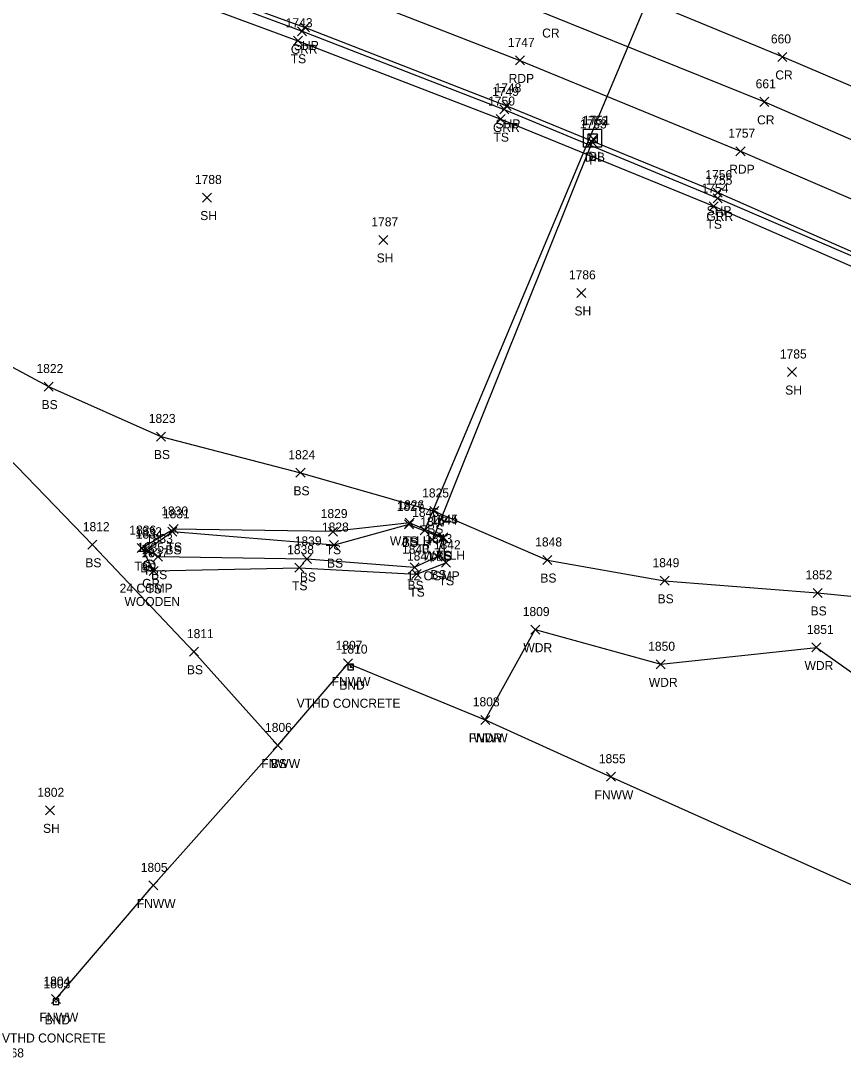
# Model space of a CAD drawing. Extents: x 1629176 to 1637209, y 606063 to 610167.
# Drawn here: x 1630075.4 to 1630257.8, y 606629.8 to 606860.2 of the extents above; entities that cross this region are included whole.
import ezdxf

# ---------------------------------------------------------------- set-up
doc = ezdxf.new("R2010")
doc.units = 0
for name, color, linetype in [('D_A', 7, 'Continuous'), ('D_C', 7, 'Continuous'), ('D_I', 7, 'Continuous'), ('D_TIC', 7, 'Continuous'), ('DCP', 7, 'Continuous'), ('DHW', 7, 'Continuous'), ('DS', 7, 'Continuous'), ('L_A', 7, 'Continuous'), ('L_I', 7, 'Continuous'), ('L_TIC', 7, 'Continuous'), ('LAWA', 7, 'Continuous'), ('LELB', 7, 'Continuous'), ('LFNC', 7, 'Continuous'), ('M_A', 7, 'Continuous'), ('M_C', 7, 'Continuous'), ('M_I', 7, 'Continuous'), ('MHBP', 7, 'Continuous'), ('P_A', 7, 'Continuous'), ('P_I', 7, 'Continuous'), ('P_TIC', 7, 'Continuous'), ('PET', 7, 'Continuous'), ('PRC', 7, 'Continuous'), ('PSP', 7, 'Continuous'), ('R_A', 7, 'Continuous'), ('R_C', 7, 'Continuous'), ('R_I', 7, 'Continuous'), ('R_TIC', 7, 'Continuous'), ('RGP', 7, 'Continuous'), ('RGR', 7, 'Continuous')]:
    doc.layers.add(name, color=color, linetype=linetype)

msp = doc.modelspace()

# ---------------------------------------------------------------- linework, layer by layer
at = {"layer": 'D_TIC'}
for points in [[(1630201.13, 606832.36), (1630203.13, 606834.36)], [(1630203.13, 606832.36), (1630201.13, 606834.36)], [(1630201.42, 606833.03), (1630203.42, 606835.03)], [(1630203.42, 606833.03), (1630201.42, 606835.03)], [(1630160.72, 606747.95), (1630162.72, 606749.95)], [(1630162.72, 606747.95), (1630160.72, 606749.95)], [(1630163.99, 606746.26), (1630165.99, 606748.26)], [(1630165.99, 606746.26), (1630163.99, 606748.26)], [(1630168.14, 606744.76), (1630170.14, 606746.76)], [(1630170.14, 606744.76), (1630168.14, 606746.76)], [(1630165.75, 606744.2), (1630167.75, 606746.2)], [(1630167.75, 606744.2), (1630165.75, 606746.2)], [(1630102.64, 606741.46), (1630104.64, 606743.46)], [(1630104.64, 606741.46), (1630102.64, 606743.46)]]:
    msp.add_lwpolyline(points, dxfattribs=at)
at = {"layer": 'DCP'}
for points in [[(1630261.59, 606976.98), (1630164.99, 606747.26)], [(1630202.13, 606833.36), (1630166.75, 606745.2)]]:
    msp.add_lwpolyline(points, dxfattribs=at)
at = {"layer": 'DHW'}
msp.add_lwpolyline([(1630161.72, 606748.95), (1630169.14, 606745.76)], dxfattribs=at)
at = {"layer": 'DS'}
for p, q in [((1630200.24, 606836.18), (1630204.24, 606836.18)), ((1630200.24, 606832.18), (1630200.24, 606836.18)), ((1630201.24, 606833.18), (1630201.24, 606835.18)), ((1630201.24, 606835.18), (1630203.24, 606835.18)), ((1630202.25, 606834.18), (1630202.25, 606834.18)), ((1630202.25, 606834.18), (1630202.25, 606834.18)), ((1630203.24, 606835.18), (1630203.24, 606833.18)), ((1630204.24, 606836.18), (1630204.24, 606832.18)), ((1630204.24, 606832.18), (1630200.24, 606832.18)), ((1630203.24, 606833.18), (1630201.24, 606833.18))]:
    msp.add_line(p, q, dxfattribs=at)
at = {"layer": 'L_TIC'}
for points in [[(1630135.9, 606854.8), (1630137.9, 606856.8)], [(1630137.9, 606854.8), (1630135.9, 606856.8)], [(1630180.87, 606837.43), (1630182.87, 606839.43)], [(1630182.87, 606837.43), (1630180.87, 606839.43)], [(1630115.76, 606820.05), (1630117.76, 606822.05)], [(1630117.76, 606820.05), (1630115.76, 606822.05)], [(1630228.1, 606818.13), (1630230.1, 606820.13)], [(1630230.1, 606818.13), (1630228.1, 606820.13)], [(1630154.88, 606810.66), (1630156.88, 606812.66)], [(1630156.88, 606810.66), (1630154.88, 606812.66)], [(1630198.74, 606798.91), (1630200.74, 606800.91)], [(1630200.74, 606798.91), (1630198.74, 606800.91)], [(1630245.47, 606781.37), (1630247.47, 606783.37)], [(1630247.47, 606781.37), (1630245.47, 606783.37)], [(1630080.62, 606778.15), (1630082.62, 606780.15)], [(1630082.62, 606778.15), (1630080.62, 606780.15)], [(1630105.52, 606767.08), (1630107.52, 606769.08)], [(1630107.52, 606767.08), (1630105.52, 606769.08)], [(1630136.48, 606759.05), (1630138.48, 606761.05)], [(1630138.48, 606759.05), (1630136.48, 606761.05)], [(1630166.15, 606750.57), (1630168.15, 606752.57)], [(1630168.15, 606750.57), (1630166.15, 606752.57)], [(1630160.52, 606747.6), (1630162.52, 606749.6)], [(1630162.52, 606747.6), (1630160.52, 606749.6)], [(1630160.52, 606747.6), (1630162.52, 606749.6)], [(1630162.52, 606747.6), (1630160.52, 606749.6)], [(1630160.72, 606747.95), (1630162.72, 606749.95)], [(1630162.72, 606747.95), (1630160.72, 606749.95)], [(1630108.09, 606745.96), (1630110.09, 606747.96)], [(1630110.09, 606745.96), (1630108.09, 606747.96)], [(1630108.38, 606746.58), (1630110.38, 606748.58)], [(1630110.38, 606746.58), (1630108.38, 606748.58)], [(1630143.66, 606746), (1630145.66, 606748)], [(1630145.66, 606746), (1630143.66, 606748)], [(1630168.06, 606744.53), (1630170.06, 606746.53)], [(1630170.06, 606744.53), (1630168.06, 606746.53)], [(1630168.06, 606744.53), (1630170.06, 606746.53)], [(1630170.06, 606744.53), (1630168.06, 606746.53)], [(1630168.14, 606744.76), (1630170.14, 606746.76)], [(1630170.14, 606744.76), (1630168.14, 606746.76)], [(1630090.33, 606743.1), (1630092.33, 606745.1)], [(1630092.33, 606743.1), (1630090.33, 606745.1)], [(1630101.27, 606742.34), (1630103.27, 606744.34)], [(1630103.27, 606742.34), (1630101.27, 606744.34)], [(1630143.92, 606743.01), (1630145.92, 606745.01)], [(1630145.92, 606743.01), (1630143.92, 606745.01)], [(1630102.5, 606741.97), (1630104.5, 606743.97)], [(1630104.5, 606741.97), (1630102.5, 606743.97)], [(1630104.91, 606740.46), (1630106.91, 606742.46)], [(1630106.91, 606740.46), (1630104.91, 606742.46)], [(1630137.9, 606739.94), (1630139.9, 606741.94)], [(1630139.9, 606739.94), (1630137.9, 606741.94)], [(1630166.86, 606740.46), (1630168.86, 606742.46)], [(1630168.86, 606740.46), (1630166.86, 606742.46)], [(1630136.2, 606738), (1630138.2, 606740)], [(1630138.2, 606738), (1630136.2, 606740)], [(1630161.77, 606738.1), (1630163.77, 606740.1)], [(1630163.77, 606738.1), (1630161.77, 606740.1)], [(1630168.73, 606739.09), (1630170.73, 606741.09)], [(1630170.73, 606739.09), (1630168.73, 606741.09)], [(1630191.23, 606739.71), (1630193.23, 606741.71)], [(1630193.23, 606739.71), (1630191.23, 606741.71)], [(1630103.91, 606737.3), (1630105.91, 606739.3)], [(1630105.91, 606737.3), (1630103.91, 606739.3)], [(1630162.2, 606736.58), (1630164.2, 606738.58)], [(1630164.2, 606736.58), (1630162.2, 606738.58)], [(1630217.23, 606735.11), (1630219.23, 606737.11)], [(1630219.23, 606735.11), (1630217.23, 606737.11)], [(1630251.15, 606732.42), (1630253.15, 606734.42)], [(1630253.15, 606732.42), (1630251.15, 606734.42)], [(1630188.54, 606724.28), (1630190.54, 606726.28)], [(1630190.54, 606724.28), (1630188.54, 606726.28)], [(1630112.85, 606719.39), (1630114.85, 606721.39)], [(1630114.85, 606719.39), (1630112.85, 606721.39)], [(1630250.89, 606720.32), (1630252.89, 606722.32)], [(1630252.89, 606720.32), (1630250.89, 606722.32)], [(1630147.03, 606716.8), (1630149.03, 606718.8)], [(1630149.03, 606716.8), (1630147.03, 606718.8)], [(1630216.36, 606716.59), (1630218.36, 606718.59)], [(1630218.36, 606716.59), (1630216.36, 606718.59)], [(1630177.45, 606704.28), (1630179.45, 606706.28)], [(1630179.45, 606704.28), (1630177.45, 606706.28)], [(1630177.45, 606704.28), (1630179.45, 606706.28)], [(1630179.45, 606704.28), (1630177.45, 606706.28)], [(1630131.44, 606698.6), (1630133.44, 606700.6)], [(1630133.44, 606698.6), (1630131.44, 606700.6)], [(1630131.44, 606698.6), (1630133.44, 606700.6)], [(1630133.44, 606698.6), (1630131.44, 606700.6)], [(1630205.32, 606691.67), (1630207.32, 606693.67)], [(1630207.32, 606691.67), (1630205.32, 606693.67)], [(1630080.91, 606684.23), (1630082.91, 606686.23)], [(1630082.91, 606684.23), (1630080.91, 606686.23)], [(1630103.82, 606667.58), (1630105.82, 606669.58)], [(1630105.82, 606667.58), (1630103.82, 606669.58)], [(1630082.24, 606642.38), (1630084.24, 606644.38)], [(1630084.24, 606642.38), (1630082.24, 606644.38)]]:
    msp.add_lwpolyline(points, dxfattribs=at)
at = {"layer": 'LAWA'}
msp.add_lwpolyline([(1630178.45, 606705.28), (1630189.54, 606725.28), (1630217.36, 606717.59), (1630251.89, 606721.32), (1630267.08, 606710.61), (1630267, 606665.5)], dxfattribs=at)
at = {"layer": 'LELB'}
for points in [[(1630044.25, 606889.35), (1630091.41, 606872.59), (1630136.9, 606855.8), (1630181.87, 606838.43), (1630229.1, 606819.13), (1630265.76, 606803.15), (1630304.81, 606785.31), (1630348.18, 606765.13), (1630385.69, 606747.11), (1630426.71, 606726.12), (1630450.89, 606713.6)], [(1630053.59, 606794.16), (1630081.62, 606779.15), (1630106.52, 606768.08), (1630137.48, 606760.05), (1630167.15, 606751.57), (1630192.23, 606740.71), (1630218.23, 606736.11), (1630252.15, 606733.42), (1630290.4, 606729.57), (1630313.6, 606719.08), (1630348.91, 606706.34), (1630395.46, 606688.14), (1630428.07, 606669.89), (1630459.56, 606655.15)], [(1630132.44, 606699.6), (1630113.85, 606720.39), (1630091.33, 606744.1), (1630068.26, 606767.89)], [(1630161.72, 606748.95), (1630144.66, 606747), (1630109.38, 606747.58), (1630102.27, 606743.34), (1630104.91, 606738.3), (1630137.2, 606739), (1630163.2, 606737.58), (1630169.73, 606740.09), (1630169.14, 606745.76)], [(1630161.52, 606748.6), (1630144.92, 606744.01), (1630109.09, 606746.96), (1630103.5, 606742.97), (1630105.91, 606741.46), (1630138.9, 606740.94), (1630162.77, 606739.1), (1630167.86, 606741.46), (1630169.06, 606745.53)], [(1630161.52, 606748.6), (1630169.06, 606745.53)]]:
    msp.add_lwpolyline(points, dxfattribs=at)
at = {"layer": 'LFNC'}
msp.add_lwpolyline([(1630083.24, 606643.38), (1630104.82, 606668.58), (1630132.44, 606699.6), (1630148.03, 606717.8), (1630178.45, 606705.28), (1630206.32, 606692.67), (1630267, 606665.5), (1630297.13, 606649.31), (1630336.07, 606632.29), (1630377.56, 606610.95), (1630421.19, 606588.3), (1630449.11, 606572.58), (1630476.9, 606556.84), (1630504.46, 606540.78), (1630518.72, 606532.31), (1630544.56, 606516.77), (1630586.07, 606490.29), (1630617.62, 606470.71), (1630638.04, 606457.74), (1630683.84, 606426.78)], dxfattribs=at)
at = {"layer": 'MHBP'}
for p, q in [((1630149.25, 606717.62), (1630148, 606717.62)), ((1630148, 606717.62), (1630148, 606716.37)), ((1630149.25, 606717.62), (1630148, 606717.62)), ((1630148, 606717.62), (1630148, 606716.37)), ((1630149.25, 606716.37), (1630149.25, 606717.62)), ((1630149.25, 606716.37), (1630149.25, 606717.62)), ((1630148, 606716.37), (1630149.25, 606716.37)), ((1630148, 606716.37), (1630149.25, 606716.37)), ((1630083.91, 606643.43), (1630082.66, 606643.43)), ((1630082.66, 606643.43), (1630082.66, 606642.18)), ((1630083.91, 606643.43), (1630082.66, 606643.43)), ((1630082.66, 606643.43), (1630082.66, 606642.18)), ((1630083.91, 606642.18), (1630083.91, 606643.43)), ((1630083.91, 606642.18), (1630083.91, 606643.43)), ((1630082.66, 606642.18), (1630083.91, 606642.18)), ((1630082.66, 606642.18), (1630083.91, 606642.18))]:
    msp.add_line(p, q, dxfattribs=at)
for centre in [(1630148.61, 606716.95), (1630083.26, 606642.77)]:
    msp.add_circle(centre, 0.0833, dxfattribs=at)
at = {"layer": 'P_TIC'}
for points in [[(1630137.49, 606857.75), (1630139.49, 606859.75)], [(1630139.49, 606857.75), (1630137.49, 606859.75)], [(1630185.15, 606850.44), (1630187.15, 606852.44)], [(1630187.15, 606850.44), (1630185.15, 606852.44)], [(1630243.34, 606851.21), (1630245.34, 606853.21)], [(1630245.34, 606851.21), (1630243.34, 606853.21)], [(1630239.3, 606841.26), (1630241.3, 606843.26)], [(1630241.3, 606841.26), (1630239.3, 606843.26)], [(1630182.19, 606840.37), (1630184.19, 606842.37)], [(1630184.19, 606840.37), (1630182.19, 606842.37)], [(1630234.05, 606830.31), (1630236.05, 606832.31)], [(1630236.05, 606830.31), (1630234.05, 606832.31)], [(1630229, 606821.13), (1630231, 606823.13)], [(1630231, 606821.13), (1630229, 606823.13)]]:
    msp.add_lwpolyline(points, dxfattribs=at)
at = {"layer": 'PET'}
msp.add_lwpolyline([(1630050.76, 606901.68), (1630096.23, 606885.67), (1630143.35, 606868.08), (1630186.15, 606851.44), (1630235.05, 606831.31), (1630271.1, 606815.81), (1630310.69, 606798.07), (1630353.79, 606777.93), (1630392.73, 606758.86), (1630432.29, 606738.62), (1630464.02, 606722.09), (1630502.44, 606701.07), (1630537.98, 606680.83), (1630570.03, 606662.27), (1630609.11, 606638.58), (1630644.7, 606616.38), (1630681.38, 606592.72), (1630715.14, 606570.86), (1630750.81, 606547.81)], dxfattribs=at)
at = {"layer": 'PRC'}
for points in [[(1630762, 606568.31), (1630732.48, 606587.66), (1630693.14, 606613.4), (1630657.5, 606636.16), (1630615.44, 606661.97), (1630565.18, 606692.12), (1630533.4, 606710.56), (1630491.42, 606733.47), (1630450.45, 606755.19), (1630412.78, 606774.87), (1630369.5, 606796.13), (1630328.6, 606815.23), (1630283.03, 606835.75), (1630244.34, 606852.21), (1630197.18, 606871.73), (1630154.28, 606888.46), (1630110.18, 606905.77), (1630065.36, 606921.68)], [(1630755.45, 606559.52), (1630726, 606578.65), (1630686.27, 606604.3), (1630651.63, 606626.53), (1630610.5, 606651.79), (1630559.24, 606682.64), (1630527.45, 606700.94), (1630485.76, 606723.98), (1630445.96, 606745.41), (1630407.11, 606765.59), (1630364.16, 606786.66), (1630323.37, 606805.55), (1630278.9, 606825.47), (1630240.3, 606842.26), (1630192.63, 606861.5), (1630149.2, 606878.91), (1630105.99, 606894.95), (1630061.18, 606910.94)]]:
    msp.add_lwpolyline(points, dxfattribs=at)
at = {"layer": 'PSP'}
msp.add_lwpolyline([(1630045.28, 606892.75), (1630092.08, 606875.64), (1630138.49, 606858.75), (1630183.19, 606841.37), (1630230, 606822.13), (1630266.88, 606805.89), (1630306.04, 606788.47), (1630348.79, 606768.34), (1630387.17, 606749.74), (1630427.91, 606728.87), (1630457.64, 606713.36), (1630497.17, 606691.94), (1630531.87, 606672.45), (1630564.31, 606653.82), (1630602.72, 606629.92), (1630638.6, 606607.1), (1630675.39, 606583.77), (1630709.63, 606561.3), (1630744.78, 606538.28)], dxfattribs=at)
at = {"layer": 'R_TIC'}
for points in [[(1630136.84, 606856.9), (1630138.84, 606858.9)], [(1630138.84, 606856.9), (1630136.84, 606858.9)], [(1630181.67, 606839.57), (1630183.67, 606841.57)], [(1630183.67, 606839.57), (1630181.67, 606841.57)], [(1630229.01, 606819.88), (1630231.01, 606821.88)], [(1630231.01, 606819.88), (1630229.01, 606821.88)]]:
    msp.add_lwpolyline(points, dxfattribs=at)
at = {"layer": 'RGP'}
msp.add_line((1630103.94, 606739.52), (1630103.94, 606739.52), dxfattribs=at)
for radius in [1.25, 0.0833]:
    msp.add_circle((1630103.94, 606739.52), radius, dxfattribs=at)
at = {"layer": 'RGR'}
msp.add_lwpolyline([(1630044.87, 606891.43), (1630091.95, 606875), (1630137.84, 606857.9), (1630182.67, 606840.57), (1630230.01, 606820.88), (1630266.36, 606805.24), (1630305.77, 606787.45), (1630348.91, 606767.39), (1630386.68, 606748.91), (1630427.72, 606728.18), (1630457.43, 606712.48), (1630496.65, 606691.24), (1630531.18, 606671.77), (1630563.73, 606652.86), (1630574.41, 606646.66), (1630584.49, 606638.94), (1630594.27, 606630.4)], dxfattribs=at)

# ---------------------------------------------------------------- texts
at = {"layer": 'D_A'}
for s, p in [('DIB', (1630200.53, 606829.03)), ('DI', (1630201.3, 606829.18)), ('P', (1630201.5, 606828.36)), ('WALLH', (1630157.31, 606743.95)), ('P', (1630164.36, 606742.26)), ('WALLH', (1630164.73, 606740.76)), ('P', (1630166.12, 606740.2)), ('P', (1630103.02, 606737.46))]:
    msp.add_text(s, height=2, dxfattribs=at).set_placement(p)
at = {"layer": 'D_C'}
for s, p in [('12 CGMP', (1630161.04, 606736.2)), ('24 CGMP', (1630097.37, 606733.46))]:
    msp.add_text(s, height=2, dxfattribs=at).set_placement(p)
at = {"layer": 'D_I'}
for s, p in [('1752', (1630199.73, 606837.03)), ('1751', (1630200.12, 606837.18)), ('1753', (1630199.43, 606836.36)), ('1826', (1630158.97, 606751.95)), ('1846', (1630162.24, 606750.26)), ('1847', (1630164.05, 606748.2)), ('1845', (1630166.45, 606748.76)), ('1834', (1630100.95, 606745.46))]:
    msp.add_text(s, height=2, dxfattribs=at).set_placement(p)
at = {"layer": 'L_A'}
for s, p in [('TS', (1630135.31, 606850.8)), ('TS', (1630180.28, 606833.43)), ('SH', (1630115.24, 606816.05)), ('TS', (1630227.51, 606814.13)), ('SH', (1630154.37, 606806.66)), ('SH', (1630198.23, 606794.91)), ('SH', (1630244.96, 606777.37)), ('BS', (1630080.06, 606774.15)), ('BS', (1630104.97, 606763.08)), ('BS', (1630135.92, 606755.05)), ('BS', (1630165.59, 606746.57)), ('TS', (1630107.79, 606742.58)), ('BS', (1630159.97, 606743.6)), ('BS', (1630159.97, 606743.6)), ('TS', (1630160.13, 606743.95)), ('BS', (1630107.53, 606741.96)), ('TS', (1630143.07, 606742)), ('TS', (1630167.55, 606740.76)), ('BS', (1630167.5, 606740.53)), ('BS', (1630167.5, 606740.53)), ('BS', (1630089.77, 606739.1)), ('TS', (1630100.68, 606738.34)), ('BS', (1630101.94, 606737.97)), ('BS', (1630143.36, 606739.01)), ('BS', (1630104.35, 606736.46)), ('BS', (1630137.34, 606735.94)), ('BS', (1630166.3, 606736.46)), ('BS', (1630190.67, 606735.71)), ('TS', (1630103.32, 606733.3)), ('TS', (1630135.61, 606734)), ('BS', (1630161.21, 606734.1)), ('TS', (1630168.14, 606735.09)), ('TS', (1630161.61, 606732.58)), ('BS', (1630216.67, 606731.11)), ('BS', (1630250.59, 606728.42)), ('WDR', (1630186.9, 606720.28)), ('BS', (1630112.29, 606715.39)), ('WDR', (1630249.25, 606716.32)), ('FNWW', (1630144.38, 606712.8)), ('WDR', (1630214.72, 606712.59)), ('FNWW', (1630174.8, 606700.28)), ('WDR', (1630175.82, 606700.28)), ('FNWW', (1630128.78, 606694.6)), ('BS', (1630130.88, 606694.6)), ('FNWW', (1630202.67, 606687.67)), ('SH', (1630080.39, 606680.23)), ('FNWW', (1630101.17, 606663.58)), ('FNWW', (1630079.59, 606638.38))]:
    msp.add_text(s, height=2, dxfattribs=at).set_placement(p)
at = {"layer": 'L_I'}
for s, p in [('1743', (1630134.2, 606858.8)), ('1750', (1630179.09, 606841.43)), ('1788', (1630114.06, 606824.05)), ('1754', (1630226.41, 606822.13)), ('1787', (1630153.19, 606814.66)), ('1786', (1630197, 606802.91)), ('1785', (1630243.78, 606785.37)), ('1822', (1630078.93, 606782.15)), ('1823', (1630103.83, 606771.08)), ('1824', (1630134.79, 606763.05)), ('1825', (1630164.46, 606754.57)), ('1827', (1630158.83, 606751.6)), ('1827', (1630158.83, 606751.6)), ('1826', (1630158.97, 606751.95)), ('1830', (1630106.6, 606750.58)), ('1831', (1630106.96, 606749.96)), ('1829', (1630141.96, 606750)), ('1812', (1630089.2, 606747.1)), ('1828', (1630142.23, 606747.01)), ('1844', (1630166.37, 606748.53)), ('1844', (1630166.37, 606748.53)), ('1845', (1630166.45, 606748.76)), ('1836', (1630099.52, 606746.34)), ('1832', (1630100.81, 606745.97)), ('1833', (1630103.22, 606744.46)), ('1843', (1630165.16, 606744.46)), ('1839', (1630136.2, 606743.94)), ('1840', (1630159.99, 606742.1)), ('1842', (1630167.04, 606743.09)), ('1848', (1630189.53, 606743.71)), ('1837', (1630102.22, 606741.3)), ('1838', (1630134.51, 606742)), ('1841', (1630161.08, 606740.58)), ('1849', (1630215.53, 606739.11)), ('1852', (1630249.46, 606736.42)), ('1809', (1630186.76, 606728.28)), ('1851', (1630249.76, 606724.32)), ('1811', (1630112.29, 606723.39)), ('1807', (1630145.26, 606720.8)), ('1850', (1630214.58, 606720.59)), ('1808', (1630175.68, 606708.28)), ('1808', (1630175.68, 606708.28)), ('1806', (1630129.61, 606702.6)), ('1806', (1630129.61, 606702.6)), ('1855', (1630203.63, 606695.67)), ('1802', (1630079.13, 606688.23)), ('1805', (1630102.05, 606671.58)), ('1804', (1630080.47, 606646.38)), ('1668', (1630070.2, 606630.47))]:
    msp.add_text(s, height=2, dxfattribs=at).set_placement(p)
at = {"layer": 'M_A'}
for p in [(1630146.09, 606711.96), (1630080.75, 606637.77)]:
    msp.add_text('BND', height=2, dxfattribs=at).set_placement(p)
at = {"layer": 'M_C'}
for p in [(1630136.62, 606707.96), (1630071.28, 606633.77)]:
    msp.add_text('VTHD CONCRETE', height=2, dxfattribs=at).set_placement(p)
at = {"layer": 'M_I'}
for s, p in [('1810', (1630146.39, 606719.96)), ('1803', (1630080.49, 606645.77))]:
    msp.add_text(s, height=2, dxfattribs=at).set_placement(p)
at = {"layer": 'P_A'}
for s, p in [('CR', (1630191.07, 606856.5)), ('SHP', (1630136.02, 606853.75)), ('RDP', (1630183.64, 606846.44)), ('CR', (1630242.77, 606847.21)), ('CR', (1630238.73, 606837.26)), ('SHP', (1630180.73, 606836.37)), ('RDP', (1630232.54, 606826.31)), ('SHP', (1630227.54, 606817.13))]:
    msp.add_text(s, height=2, dxfattribs=at).set_placement(p)
at = {"layer": 'P_I'}
for s, p in [('660', (1630241.79, 606855.21)), ('1747', (1630183.46, 606854.44)), ('1748', (1630180.5, 606844.37)), ('661', (1630238.41, 606845.26)), ('1757', (1630232.36, 606834.31)), ('1756', (1630227.25, 606825.13))]:
    msp.add_text(s, height=2, dxfattribs=at).set_placement(p)
at = {"layer": 'R_A'}
for s, p in [('GRR', (1630135.33, 606852.9)), ('GRR', (1630180.16, 606835.57)), ('GRR', (1630227.49, 606815.88)), ('GP', (1630102.37, 606734.52))]:
    msp.add_text(s, height=2, dxfattribs=at).set_placement(p)
at = {"layer": 'R_C'}
msp.add_text('WOODEN', height=2, dxfattribs=at).set_placement((1630098.45, 606730.52))
at = {"layer": 'R_I'}
for s, p in [('1749', (1630179.97, 606843.57)), ('1755', (1630227.31, 606823.88)), ('1835', (1630101.25, 606742.52))]:
    msp.add_text(s, height=2, dxfattribs=at).set_placement(p)

doc.saveas('drawing.dxf')
